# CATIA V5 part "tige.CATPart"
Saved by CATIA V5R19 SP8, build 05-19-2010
Part number: tige
Publications: "axetige", "axeEbis"
Bounding box of the stored display mesh (mm): x -20 to 20, y 0 to 200, z 0 to 0
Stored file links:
  C:\Users\rcousturie\Desktop\EU_thinkMotion\iao\IAO_MMS_Groupe1\flamrini\Lamrini_projet_IAO2011\Lamrini_projet_IAO2011\projet_iao_traindatterrissage\projet_iao_traindatterrissage\tige.CATPart
  C:\Users\rcousturie\Desktop\EU_thinkMotion\iao\IAO_MMS_Groupe1\flamrini\Lamrini_projet_IAO2011\Lamrini_projet_IAO2011\projet_iao_traindatterrissage\projet_iao_traindatterrissage\squelettetrain.CATProduct
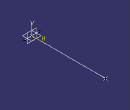
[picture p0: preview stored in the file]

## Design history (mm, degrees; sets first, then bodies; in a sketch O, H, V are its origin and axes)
Set1
  Point1 "PointE": linked copy from another document
  Point2 "PointF": linked copy from another document
Set2 "Set géométrique.4"
  Line1 "axetige": type PtPt, FirstPoint Point1, SecondPoint Point2
  Line2 "axeEbis": type PtDir, RefPoint Point1, Direction yz-plane, Start -20, End 20
  Sketch1 on yz-plane, origin (0, 0, 0), H (0, 1, 0), V (0, 0, 1)
Body1 (main body)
